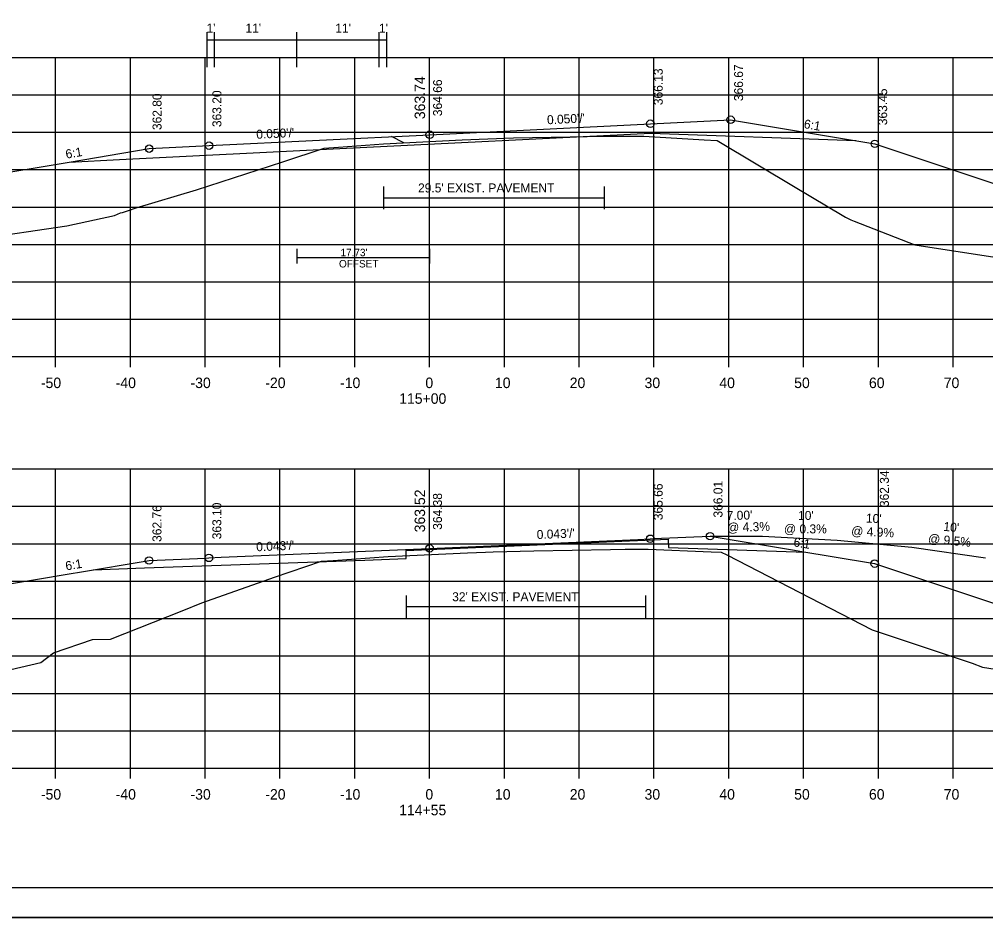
# Model space of a CAD drawing. Extents: x 1374859 to 1376773, y 382242 to 389804.
# Drawn here: x 1376555.6 to 1376684.8, y 383308.4 to 383428.5 of the extents above; entities that cross this region are included whole.
import ezdxf

# ---------------------------------------------------------------- set-up
doc = ezdxf.new("R2010")
doc.units = 0
for name, color, linetype in [('R_Axis', 7, 'Continuous'), ('R_Axis Annot', 7, 'Continuous'), ('R_Border', 7, 'Continuous'), ('R_Border Notes', 7, 'Continuous'), ('R_Draft', 7, 'Continuous'), ('R_Drive', 7, 'Continuous'), ('R_Exist Surface', 7, 'Continuous'), ('R_Fin Surface', 7, 'Continuous'), ('R_Grid', 7, 'Continuous'), ('R_MOT', 7, 'Continuous'), ('R_No Plot', 7, 'Continuous'), ('R_Xsect Elev', 7, 'Continuous'), ('R_Xsect Slope', 7, 'Continuous')]:
    doc.layers.add(name, color=color, linetype=linetype)

msp = doc.modelspace()

# ---------------------------------------------------------------- linework, layer by layer
at = {"layer": 'R_Axis'}
for p, q in [((1376470.45, 383383.41), (1376750.45, 383383.41)), ((1376560.45, 383382.01), (1376560.45, 383383.41)), ((1376570.45, 383382.01), (1376570.45, 383383.41)), ((1376580.45, 383382.01), (1376580.45, 383383.41)), ((1376590.45, 383382.01), (1376590.45, 383383.41)), ((1376600.45, 383382.01), (1376600.45, 383383.41)), ((1376610.45, 383382.01), (1376610.45, 383383.41)), ((1376620.45, 383382.01), (1376620.45, 383383.41)), ((1376630.45, 383382.01), (1376630.45, 383383.41)), ((1376640.45, 383382.01), (1376640.45, 383383.41)), ((1376650.45, 383382.01), (1376650.45, 383383.41)), ((1376660.45, 383382.01), (1376660.45, 383383.41)), ((1376670.45, 383382.01), (1376670.45, 383383.41)), ((1376680.45, 383382.01), (1376680.45, 383383.41)), ((1376470.45, 383328.41), (1376750.45, 383328.41)), ((1376560.45, 383327.01), (1376560.45, 383328.41)), ((1376570.45, 383327.01), (1376570.45, 383328.41)), ((1376580.45, 383327.01), (1376580.45, 383328.41)), ((1376590.45, 383327.01), (1376590.45, 383328.41)), ((1376600.45, 383327.01), (1376600.45, 383328.41)), ((1376610.45, 383327.01), (1376610.45, 383328.41)), ((1376620.45, 383327.01), (1376620.45, 383328.41)), ((1376630.45, 383327.01), (1376630.45, 383328.41)), ((1376640.45, 383327.01), (1376640.45, 383328.41)), ((1376650.45, 383327.01), (1376650.45, 383328.41)), ((1376660.45, 383327.01), (1376660.45, 383328.41)), ((1376670.45, 383327.01), (1376670.45, 383328.41)), ((1376680.45, 383327.01), (1376680.45, 383328.41))]:
    msp.add_line(p, q, dxfattribs=at)
at = {"layer": 'R_Border'}
msp.add_line((1376768.63, 383312.41), (1376452.45, 383312.41), dxfattribs=at)
at = {"layer": 'R_Border Notes'}
msp.add_line((1376633.79, 383406.14), (1376633.79, 383403.14), dxfattribs=at)
for points in [[(1376604.29, 383406.14), (1376604.29, 383403.14)], [(1376604.29, 383404.64), (1376633.79, 383404.64)], [(1376607.32, 383351.5), (1376607.32, 383348.5)], [(1376639.32, 383351.5), (1376639.32, 383348.5)], [(1376607.32, 383350), (1376639.32, 383350)]]:
    msp.add_lwpolyline(points, dxfattribs=at)
at = {"layer": 'R_Drive'}
for p, q in [((1376607.02, 383411.98), (1376605.34, 383412.82)), ((1376647.95, 383359.42), (1376654.95, 383359.4)), ((1376654.95, 383359.4), (1376664.94, 383358.9)), ((1376664.94, 383358.9), (1376674.9, 383357.95)), ((1376674.9, 383357.95), (1376684.79, 383356.53))]:
    msp.add_line(p, q, dxfattribs=at)
at = {"layer": 'R_Exist Surface'}
for points in [[(1376549.83, 383399.1), (1376561.98, 383400.9), (1376568.31, 383402.27), (1376569.12, 383402.63), (1376569.38, 383402.69), (1376569.66, 383402.78), (1376570.22, 383402.93), (1376571.24, 383403.3), (1376579.29, 383405.69), (1376590.84, 383409.44), (1376596.37, 383411.27), (1376598.28, 383411.41), (1376604.29, 383411.85), (1376614.82, 383412.37), (1376618.22, 383412.54), (1376619.4, 383412.57), (1376621.65, 383412.65), (1376629.23, 383412.78), (1376633.78, 383412.87), (1376635.41, 383412.87), (1376639.08, 383412.86), (1376647.14, 383412.38), (1376648.91, 383412.28), (1376659.54, 383405.95), (1376665.6, 383402.34), (1376666.04, 383402.06), (1376666.77, 383401.69), (1376667.23, 383401.54), (1376675.32, 383398.36), (1376690.06, 383396.08)], [(1376551.01, 383340.81), (1376558.5, 383342.53), (1376560.17, 383343.82), (1376565.37, 383345.6), (1376567.79, 383345.64), (1376577.36, 383349.42), (1376580.02, 383350.51), (1376589.73, 383353.95), (1376596, 383356.07), (1376597.56, 383356.18), (1376604.9, 383356.68), (1376615.52, 383357.17), (1376617.91, 383357.28), (1376618.93, 383357.31), (1376624.38, 383357.46), (1376634.62, 383357.65), (1376636.59, 383357.68), (1376637.76, 383357.68), (1376639.66, 383357.67), (1376648.1, 383357.33), (1376649.41, 383357.27), (1376650.21, 383356.9), (1376669.6, 383346.89), (1376682.99, 383342.44), (1376684.38, 383341.9), (1376687.75, 383341.38)]]:
    msp.add_lwpolyline(points, dxfattribs=at)
at = {"layer": 'R_Fin Surface'}
for points in [[(1376496.28, 383394.2), (1376503.61, 383391.75), (1376550.97, 383407.54), (1376562.27, 383409.42), (1376572.97, 383411.21), (1376580.97, 383411.61), (1376610.47, 383413.07), (1376639.97, 383414.54), (1376650.7, 383415.08), (1376664.32, 383412.8), (1376669.97, 383411.86), (1376722.33, 383394.41), (1376725.03, 383395.31)], [(1376562.26, 383409.42), (1376568.98, 383409.76), (1376598.46, 383411.23), (1376640.03, 383413.29)], [(1376640.03, 383413.29), (1376667.45, 383412.28)], [(1376551.6, 383352.61), (1376562.81, 383354.48), (1376563.4, 383354.58), (1376572.95, 383356.17), (1376580.5, 383356.49), (1376580.95, 383356.51), (1376582.59, 383356.59), (1376610.45, 383357.79), (1376638.27, 383358.99), (1376639.95, 383359.07), (1376640.4, 383359.09), (1376647.95, 383359.42), (1376659.24, 383357.54), (1376659.93, 383357.42), (1376669.4, 383355.84), (1376669.95, 383355.75), (1376714.12, 383341.03), (1376716.95, 383340.09), (1376717.56, 383340.29), (1376717.67, 383340.32)], [(1376565.49, 383354.92), (1376572.33, 383355.17), (1376601.81, 383356.21), (1376607.31, 383356.41), (1376607.32, 383357.49), (1376642.36, 383359.01)], [(1376642.36, 383359.01), (1376642.38, 383357.92), (1376660.73, 383357.29)]]:
    msp.add_lwpolyline(points, dxfattribs=at)
at = {"layer": 'R_Grid'}
for p, q in [((1376470.45, 383423.41), (1376750.45, 383423.41)), ((1376560.45, 383383.41), (1376560.45, 383423.41)), ((1376570.45, 383383.41), (1376570.45, 383423.41)), ((1376580.45, 383383.41), (1376580.45, 383423.41)), ((1376590.45, 383383.41), (1376590.45, 383423.41)), ((1376600.45, 383383.41), (1376600.45, 383423.41)), ((1376610.45, 383383.41), (1376610.45, 383423.41)), ((1376620.45, 383383.41), (1376620.45, 383423.41)), ((1376630.45, 383383.41), (1376630.45, 383423.41)), ((1376640.45, 383383.41), (1376640.45, 383423.41)), ((1376650.45, 383383.41), (1376650.45, 383423.41)), ((1376660.45, 383383.41), (1376660.45, 383423.41)), ((1376670.45, 383383.41), (1376670.45, 383423.41)), ((1376680.45, 383383.41), (1376680.45, 383423.41)), ((1376470.45, 383418.41), (1376750.45, 383418.41)), ((1376470.45, 383413.41), (1376750.45, 383413.41)), ((1376470.45, 383408.41), (1376750.45, 383408.41)), ((1376470.45, 383403.41), (1376750.45, 383403.41)), ((1376470.45, 383398.41), (1376750.45, 383398.41)), ((1376470.45, 383393.41), (1376750.45, 383393.41)), ((1376470.45, 383388.41), (1376750.45, 383388.41)), ((1376470.45, 383383.41), (1376750.45, 383383.41)), ((1376470.45, 383368.41), (1376750.45, 383368.41)), ((1376560.45, 383328.41), (1376560.45, 383368.41)), ((1376570.45, 383328.41), (1376570.45, 383368.41)), ((1376580.45, 383328.41), (1376580.45, 383368.41)), ((1376590.45, 383328.41), (1376590.45, 383368.41)), ((1376600.45, 383328.41), (1376600.45, 383368.41)), ((1376610.45, 383328.41), (1376610.45, 383368.41)), ((1376620.45, 383328.41), (1376620.45, 383368.41)), ((1376630.45, 383328.41), (1376630.45, 383368.41)), ((1376640.45, 383328.41), (1376640.45, 383368.41)), ((1376650.45, 383328.41), (1376650.45, 383368.41)), ((1376660.45, 383328.41), (1376660.45, 383368.41)), ((1376670.45, 383328.41), (1376670.45, 383368.41)), ((1376680.45, 383328.41), (1376680.45, 383368.41)), ((1376470.45, 383363.41), (1376750.45, 383363.41)), ((1376470.45, 383358.41), (1376750.45, 383358.41)), ((1376470.45, 383353.41), (1376750.45, 383353.41)), ((1376470.45, 383348.41), (1376750.45, 383348.41)), ((1376470.45, 383343.41), (1376750.45, 383343.41)), ((1376470.45, 383338.41), (1376750.45, 383338.41)), ((1376470.45, 383333.41), (1376750.45, 383333.41)), ((1376470.45, 383328.41), (1376750.45, 383328.41))]:
    msp.add_line(p, q, dxfattribs=at)
at = {"layer": 'R_MOT'}
for p, q in [((1376580.72, 383422.12), (1376580.72, 383426.76)), ((1376581.72, 383422.12), (1376581.72, 383426.76)), ((1376592.72, 383422.12), (1376592.72, 383426.76)), ((1376603.72, 383422.12), (1376603.72, 383426.76)), ((1376604.72, 383422.12), (1376604.72, 383426.76)), ((1376580.72, 383425.76), (1376604.72, 383425.76)), ((1376592.72, 383397.8), (1376592.72, 383395.87)), ((1376610.45, 383397.8), (1376610.45, 383395.87)), ((1376610.45, 383396.62), (1376592.72, 383396.62))]:
    msp.add_line(p, q, dxfattribs=at)
at = {"layer": 'R_No Plot'}
msp.add_line((1376440.05, 383308.43), (1376773.38, 383308.43), dxfattribs=at)
for points in [[(1376440.04, 383521.76), (1376773.38, 383521.76), (1376773.38, 383308.43), (1376440.04, 383308.43)], [(1376686.37, 383517.87), (1376686.37, 383507.99), (1376722.1, 383507.99), (1376722.1, 383505.07), (1376745.3, 383505.07), (1376745.3, 383480.74), (1376768.63, 383480.74), (1376768.63, 383312.41), (1376452.45, 383312.41), (1376452.45, 383517.87)]]:
    msp.add_lwpolyline(points, close=True, dxfattribs=at)
for centre in [(1376650.7, 383415.08), (1376639.97, 383414.54), (1376610.47, 383413.07), (1376572.97, 383411.21), (1376580.97, 383411.61), (1376669.97, 383411.86), (1376647.95, 383359.42), (1376610.45, 383357.79), (1376639.95, 383359.07), (1376580.95, 383356.51), (1376572.95, 383356.17), (1376669.95, 383355.75)]:
    msp.add_circle(centre, 0.5, dxfattribs=at)

# ---------------------------------------------------------------- texts
at = {"layer": 'R_Axis Annot'}
for s, p in [('-50', (1376558.49, 383379.21)), ('-40', (1376568.49, 383379.21)), ('-30', (1376578.49, 383379.21)), ('-20', (1376588.49, 383379.21)), ('-10', (1376598.49, 383379.21)), ('0', (1376609.89, 383379.21)), ('10', (1376619.19, 383379.21)), ('20', (1376629.19, 383379.21)), ('30', (1376639.19, 383379.21)), ('40', (1376649.19, 383379.21)), ('50', (1376659.19, 383379.21)), ('60', (1376669.19, 383379.21)), ('70', (1376679.19, 383379.21)), ('115+00', (1376606.39, 383377.11)), ('-50', (1376558.49, 383324.21)), ('-40', (1376568.49, 383324.21)), ('-30', (1376578.49, 383324.21)), ('-20', (1376588.49, 383324.21)), ('-10', (1376598.49, 383324.21)), ('0', (1376609.89, 383324.21)), ('10', (1376619.19, 383324.21)), ('20', (1376629.19, 383324.21)), ('30', (1376639.19, 383324.21)), ('40', (1376649.19, 383324.21)), ('50', (1376659.19, 383324.21)), ('60', (1376669.19, 383324.21)), ('70', (1376679.19, 383324.21)), ('114+55', (1376606.38, 383322.11))]:
    msp.add_text(s, height=1.4, dxfattribs=at).set_placement(p)
at = {"layer": 'R_Border Notes'}
for s, p in [("29.5' EXIST. PAVEMENT", (1376608.91, 383405.36)), ("32' EXIST. PAVEMENT", (1376613.47, 383350.72))]:
    msp.add_text(s, height=1.2, rotation=0, dxfattribs=at).set_placement(p)
at = {"layer": 'R_Draft'}
for s, p in [("17.73'", (1376598.54, 383396.83)), ('OFFSET', (1376598.34, 383395.33))]:
    msp.add_text(s, height=1, dxfattribs=at).set_placement(p)
at = {"layer": 'R_MOT'}
for s, p in [("1'", (1376580.63, 383426.72)), ("11'", (1376585.84, 383426.72)), ("11'", (1376597.85, 383426.72)), ("1'", (1376603.69, 383426.72))]:
    msp.add_text(s, height=1.2, dxfattribs=at).set_placement(p)
at = {"layer": 'R_Xsect Elev'}
for s, height, rotation, p in [('366.13', 1.2, 90, (1376641.62, 383417.02)), ('366.67', 1.2, 90, (1376652.36, 383417.56)), ('363.74', 1.4, 90, (1376609.85, 383415.15)), ('364.66', 1.2, 90, (1376612.12, 383415.55)), ('363.45', 1.2, 90, (1376671.62, 383414.34)), ('362.80', 1.2, 90, (1376574.62, 383413.69)), ('363.20', 1.2, 90, (1376582.62, 383414.09)), ('362.34', 1.2, 90, (1376671.85, 383363.3)), ('365.66', 1.2, 90, (1376641.61, 383361.55)), ('366.01', 1.2, 90, (1376649.61, 383361.9)), ('363.52', 1.4, 90, (1376609.85, 383359.93)), ('364.38', 1.2, 90, (1376612.11, 383360.27)), ('362.76', 1.2, 90, (1376574.61, 383358.65)), ('363.10', 1.2, 90, (1376582.61, 383359)), ("10'", 1.2, 359.8188, (1376659.71, 383361.59)), ("10'", 1.2, 357.1688, (1376668.76, 383361.24)), ('@ 0.3%', 1.2, 359.8188, (1376657.82, 383359.8)), ("10' ", 1.2, 354.5188, (1376679.1, 383360.14)), ('@ 4.9%', 1.2, 357.1688, (1376666.79, 383359.54)), ('@ 9.5%', 1.2, 354.5188, (1376677.05, 383358.53))]:
    msp.add_text(s, height=height, rotation=rotation, dxfattribs=at).set_placement(p)
at = {"layer": 'R_Xsect Slope'}
for s, rotation, p in [("0.050'/'", 2.849, (1376626.18, 383414.46)), ("0.050'/'", 2.849, (1376587.31, 383412.52)), ('6:1', 350.5358, (1376660.42, 383413.96)), ('6:1', 9.4642, (1376561.89, 383409.87)), ("7.00'", 1.8491, (1376650.19, 383361.55)), ('@ 4.3%', 1.8491, (1376650.24, 383359.96)), ("0.043'/'", 2.4821, (1376624.8, 383359.02)), ("0.043'/'", 2.4821, (1376587.3, 383357.39)), ('6:1', 350.5358, (1376659.04, 383358.08)), ('6:1', 9.4642, (1376561.87, 383354.83))]:
    msp.add_text(s, height=1.2, rotation=rotation, dxfattribs=at).set_placement(p)

doc.saveas('drawing.dxf')
